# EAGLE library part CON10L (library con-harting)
CONNECTOR
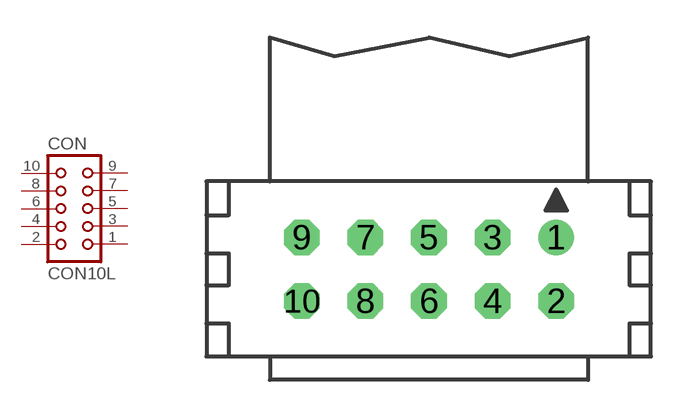
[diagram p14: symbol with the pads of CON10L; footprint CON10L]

Designator prefix CON

## CON10L (OC_FARNELL: unknown; OC_NEWARK: unknown)  [CON10L]
1  1  pas
2  2  pas
3  3  pas
4  4  pas
5  5  pas
6  6  pas
7  7  pas
8  8  pas
9  9  pas
10  10  pas

## Footprint CON10L (pad centres in mm)
CONNECTOR
drill 0.914 round: 1 5.08,1.27
drill 0.914 octagon: 2 5.08,-1.27; 3 2.54,1.27; 4 2.54,-1.27; 5 0,1.27; 6 0,-1.27; 7 -2.54,1.27; 8 -2.54,-1.27; 9 -5.08,1.27; 10 -5.08,-1.27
